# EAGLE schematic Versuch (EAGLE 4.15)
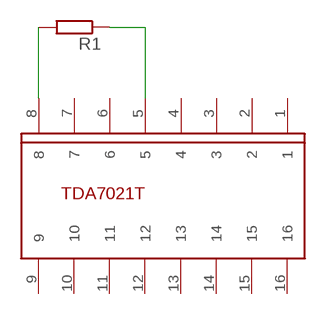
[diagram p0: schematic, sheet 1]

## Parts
R1  R-EU_0207/10  [0207/10]
U$1  TDA7021T  [SO-16]

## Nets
N$1: R1.2 U$1.8
N$2: R1.1 U$1.5
Unconnected: U$1.1 U$1.2 U$1.6 U$1.7 U$1.9 U$1.10 U$1.11 U$1.12 U$1.13 U$1.14 U$1.15 U$1.16

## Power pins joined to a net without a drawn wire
3: U$1.3
4: U$1.4

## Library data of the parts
R1 = rcl:R-EU_: RESISTOR, European symbol
U$1 = tda:TDA7021T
